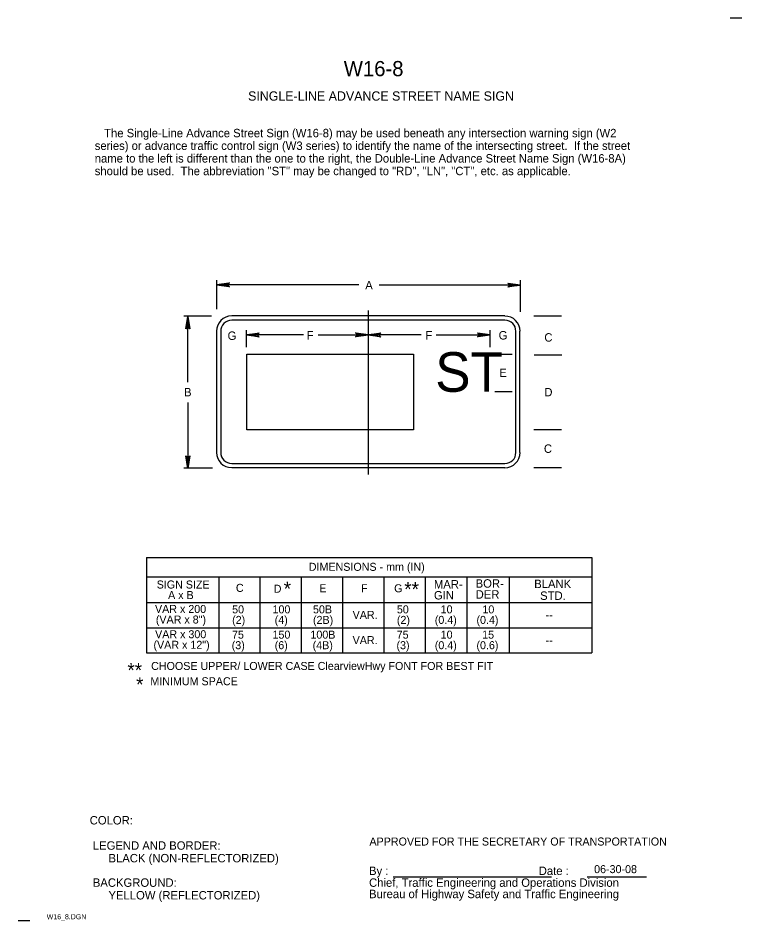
# Model space of a CAD drawing. Extents: x 0.004 to 0.219, y 0.004 to 0.272.
import ezdxf

# ---------------------------------------------------------------- set-up
doc = ezdxf.new("R2010")
doc.units = 0
for name, color, linetype in [('1', 7, 'Continuous'), ('2', 7, 'Continuous'), ('3', 7, 'Continuous'), ('4', 7, 'Continuous'), ('63', 7, 'Continuous')]:
    doc.layers.add(name, color=color, linetype=linetype)

# ---------------------------------------------------------------- blocks, each defined once
blk = doc.blocks.new('RARROW')
at = {"layer": '3'}
for p, q in [((-2.156, 0.285), (-2.2665, 0.384625)), ((-2.2665, 0.384625), (0, 0)), ((0, 0), (-2.2665, -0.379125)), ((-2.156, 0.285), (-2.075625, 0.12075)), ((0, 0), (-2.156, 0.285)), ((-2.14975, -0.2705), (0, 0)), ((-2.075625, 0.12075), (0, 0)), ((0, 0), (-2.074, -0.108)), ((-2.2665, -0.379125), (-2.14975, -0.2705)), ((-2.074, -0.108), (-2.14975, -0.2705))]:
    blk.add_line(p, q, dxfattribs=at)

msp = doc.modelspace()

# ---------------------------------------------------------------- linework, layer by layer
at = {"layer": '1'}
for p, q in [((0.108, 0.185), (0.108, 0.13637)), ((0.11544, 0.01695), (0.16242, 0.01695)), ((0.17295, 0.01695), (0.19056, 0.01695))]:
    msp.add_line(p, q, dxfattribs=at)
msp.add_lwpolyline([(0.07203, 0.17204), (0.1214, 0.17204), (0.1214, 0.14959), (0.07203, 0.14959)], close=True, dxfattribs=at)
at = {"layer": '3'}
for p, q in [((0.06313, 0.18534), (0.06313, 0.19396)), ((0.15317, 0.18459), (0.15317, 0.19396)), ((0.10518, 0.19262), (0.06313, 0.19262)), ((0.11123, 0.19257), (0.15312, 0.19257)), ((0.0615, 0.18334), (0.05329, 0.18334)), ((0.0545, 0.16372), (0.0545, 0.18334)), ((0.1485, 0.18338), (0.0675, 0.18338)), ((0.1653, 0.18334), (0.15709, 0.18334)), ((0.1485, 0.18213), (0.0675, 0.18213)), ((0.108, 0.18088), (0.108, 0.17913)), ((0.063, 0.17888), (0.063, 0.14287)), ((0.06425, 0.17888), (0.06425, 0.14287)), ((0.08878, 0.17775), (0.07188, 0.17775)), ((0.07189, 0.17409), (0.07189, 0.17913)), ((0.09312, 0.17775), (0.108, 0.17775)), ((0.12375, 0.17775), (0.108, 0.17775)), ((0.12812, 0.17775), (0.14417, 0.17775)), ((0.14417, 0.17409), (0.14417, 0.17913)), ((0.15175, 0.14287), (0.15175, 0.17888)), ((0.153, 0.14287), (0.153, 0.17888)), ((0.15075, 0.17191), (0.14556, 0.17191)), ((0.16542, 0.17173), (0.15721, 0.17173)), ((0.15075, 0.16084), (0.14556, 0.16084)), ((0.0545, 0.15767), (0.0545, 0.13821)), ((0.1653, 0.14959), (0.15709, 0.14959)), ((0.0675, 0.13962), (0.1485, 0.13962)), ((0.06185, 0.13816), (0.05327, 0.13816)), ((0.0675, 0.13837), (0.1485, 0.13837)), ((0.1653, 0.13834), (0.15709, 0.13834)), ((0.04225, 0.11175), (0.17438, 0.11175)), ((0.04225, 0.11175), (0.04225, 0.08338)), ((0.17438, 0.11175), (0.17438, 0.08338)), ((0.17438, 0.10587), (0.04225, 0.10587)), ((0.06364, 0.1058), (0.06364, 0.08338)), ((0.07589, 0.1058), (0.07589, 0.08338)), ((0.08814, 0.1058), (0.08814, 0.08338)), ((0.10039, 0.1058), (0.10039, 0.08338)), ((0.11264, 0.1058), (0.11264, 0.08338)), ((0.12489, 0.1058), (0.12489, 0.08338)), ((0.13729, 0.1058), (0.13729, 0.08338)), ((0.14984, 0.1058), (0.14984, 0.08338)), ((0.04225, 0.09838), (0.17438, 0.09838)), ((0.04225, 0.09087), (0.17438, 0.09087)), ((0.04225, 0.08338), (0.17438, 0.08338))]:
    msp.add_line(p, q, dxfattribs=at)
for centre, radius, start, end in [((0.06752, 0.17886), 0.00452, 90.2314, 180.2314), ((0.14856, 0.17884), 0.0045, 0, 90), ((0.06752, 0.17885), 0.00327, 90.3879, 180.3879), ((0.14856, 0.17884), 0.00325, 0, 90), ((0.0675, 0.14287), 0.0045, 180, 270), ((0.0675, 0.14287), 0.00325, 180, 270), ((0.14856, 0.14284), 0.0045, 270, 0), ((0.14856, 0.14284), 0.00325, 270, 0)]:
    msp.add_arc(centre, radius, start, end, dxfattribs=at)
at = {"layer": '63'}
for p, q in [((0.21888, 0.27175), (0.21538, 0.27175)), ((0.00762, 0.00387), (0.00413, 0.00387))]:
    msp.add_line(p, q, dxfattribs=at)

# ---------------------------------------------------------------- block references
at = {"layer": '3', "xscale": 0.0016545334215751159, "yscale": 0.0016366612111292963}
for p, rotation in [((0.06313, 0.19262), 180), ((0.0545, 0.18325), 90), ((0.07188, 0.17775), 180), ((0.108, 0.17775), 180), ((0.0545, 0.13812), -90)]:
    msp.add_blockref('RARROW', p, dxfattribs=dict(at, rotation=rotation))
for p in [(0.15313, 0.1925), (0.108, 0.17775), (0.14413, 0.17775)]:
    msp.add_blockref('RARROW', p, dxfattribs=at)

# ---------------------------------------------------------------- texts
at = {"layer": '1'}
for s, height, p in [('W16-8', 0.0045, (0.10075, 0.2545)), ('SINGLE-LINE ADVANCE STREET NAME SIGN', 0.0027503, (0.07237, 0.24725)), ('G', 0.0025, (0.06629, 0.17626)), ('G', 0.0025, (0.14671, 0.17638)), ('*', 0.0042, (0.08293, 0.10034)), ('**', 0.0042, (0.1187, 0.1002)), ('--', 0.002375, (0.16062, 0.0935)), ('--', 0.002375, (0.16062, 0.086)), ('CHOOSE UPPER/ LOWER CASE ClearviewHwy FONT FOR BEST FIT', 0.0023752, (0.0436, 0.07834)), ('**', 0.0042, (0.03656, 0.07616)), ('*', 0.0042, (0.03914, 0.07193)), ('MINIMUM SPACE', 0.0023752, (0.04338, 0.0738)), ('COLOR:', 0.0025, (0.02538, 0.0325)), (' LEGEND AND BORDER:', 0.0024998, (0.02538, 0.025)), ('APPROVED FOR THE SECRETARY OF TRANSPORTATION', 0.0023752, (0.10837, 0.02625)), ('      BLACK (NON-REFLECTORIZED)', 0.0024998, (0.02538, 0.02125)), ('By :                                                Date :', 0.0024998, (0.10825, 0.0175)), (' BACKGROUND:', 0.0024998, (0.02538, 0.014)), ('Chief, Traffic Engineering and Operations Division', 0.0024998, (0.10825, 0.014)), ('      YELLOW (REFLECTORIZED)', 0.0024998, (0.02538, 0.01025)), ('Bureau of Highway Safety and Traffic Engineering', 0.0024998, (0.10825, 0.01063)), ('W16_8.DGN', 0.0015, (0.01263, 0.00438))]:
    msp.add_text(s, height=height, dxfattribs=at).set_placement(p)
at = {"layer": '2'}
for s, height, p in [('   The Single-Line Advance Street Sign (W16-8) may be used beneath any intersection warning sign (W2', 0.0024998, (0.02687, 0.23638)), ('series) or advance traffic control sign (W3 series) to identify the name of the intersecting street.  If the street', 0.00249975, (0.02687, 0.23263)), ('name to the left is different than the one to the right, the Double-Line Advance Street Name Sign (W16-8A)', 0.00249975, (0.02687, 0.22888)), ('should be used.  The abbreviation "ST" may be changed to "RD", "LN", "CT", etc. as applicable.', 0.0024998, (0.02687, 0.22513))]:
    msp.add_text(s, height=height, dxfattribs=at).set_placement(p)
at = {"layer": '3'}
for s, height, p in [('A', 0.0025, (0.10712, 0.19125)), ('F', 0.0025, (0.08975, 0.17638)), ('F', 0.0025, (0.125, 0.17638)), ('C', 0.0025, (0.16025, 0.17575)), ('ST', 0.01175, (0.12788, 0.16087)), ('E', 0.0025, (0.14688, 0.16525)), ('B', 0.0025, (0.05337, 0.1595)), ('D', 0.0025, (0.16025, 0.1595)), ('C', 0.0025, (0.16012, 0.14275)), ('DIMENSIONS - mm (IN)', 0.0023752, (0.09037, 0.10775)), ('SIGN SIZE', 0.002375, (0.04525, 0.1025)), ('MAR-', 0.0025, (0.1275, 0.1025)), ('BOR-', 0.0025, (0.13987, 0.10275)), ('BLANK', 0.0025, (0.15725, 0.10263)), ('C', 0.00238, (0.06875, 0.1015)), ('D', 0.00238, (0.07997, 0.10125)), ('E', 0.00238, (0.0935, 0.10138)), ('F', 0.00238, (0.10587, 0.10138)), ('G', 0.00238, (0.1157, 0.10138)), ('DER', 0.0025, (0.13987, 0.0995)), ('A x B', 0.002375, (0.04863, 0.09938)), ('GIN', 0.0025, (0.1275, 0.09925)), ('STD.', 0.0025, (0.159, 0.09913)), ('VAR x 200', 0.002375, (0.04475, 0.09525)), ('50', 0.002375, (0.06763, 0.09513)), ('100', 0.002375, (0.07961, 0.09513)), ('50B', 0.002375, (0.09162, 0.09513)), ('50', 0.002375, (0.1165, 0.09513)), ('10', 0.002375, (0.1295, 0.09513)), ('10', 0.002375, (0.14188, 0.09513)), ('(VAR x 8")', 0.002375, (0.045, 0.09212)), ('(2)', 0.002375, (0.06763, 0.092)), ('(4)', 0.002375, (0.08026, 0.092)), ('(2B)', 0.002375, (0.09162, 0.092)), ('VAR.', 0.002375, (0.10338, 0.0935)), ('(2)', 0.002375, (0.1165, 0.092)), ('(0.4)', 0.002375, (0.12775, 0.092)), ('(0.4)', 0.002375, (0.14012, 0.092)), ('VAR x 300', 0.002375, (0.04478, 0.08775)), ('75', 0.002375, (0.06759, 0.08763)), ('150', 0.002375, (0.07961, 0.08763)), ('100B', 0.002375, (0.09086, 0.08763)), ('75', 0.002375, (0.11646, 0.08763)), ('10', 0.002375, (0.1295, 0.08763)), ('15', 0.002375, (0.14181, 0.08763)), ('(VAR x 12")', 0.0023752, (0.0443, 0.08462)), ('(3)', 0.002375, (0.06751, 0.0845)), ('(6)', 0.002375, (0.08026, 0.0845)), ('(4B)', 0.002375, (0.09152, 0.0845)), ('VAR.', 0.002375, (0.10338, 0.086)), ('(3)', 0.002375, (0.11639, 0.0845)), ('(0.4)', 0.002375, (0.12775, 0.0845)), ('(0.6)', 0.002375, (0.14011, 0.0845))]:
    msp.add_text(s, height=height, dxfattribs=at).set_placement(p)
at = {"layer": '4'}
msp.add_text('06-30-08', height=0.002375, dxfattribs=at).set_placement((0.17502, 0.01806))

doc.saveas('drawing.dxf')
